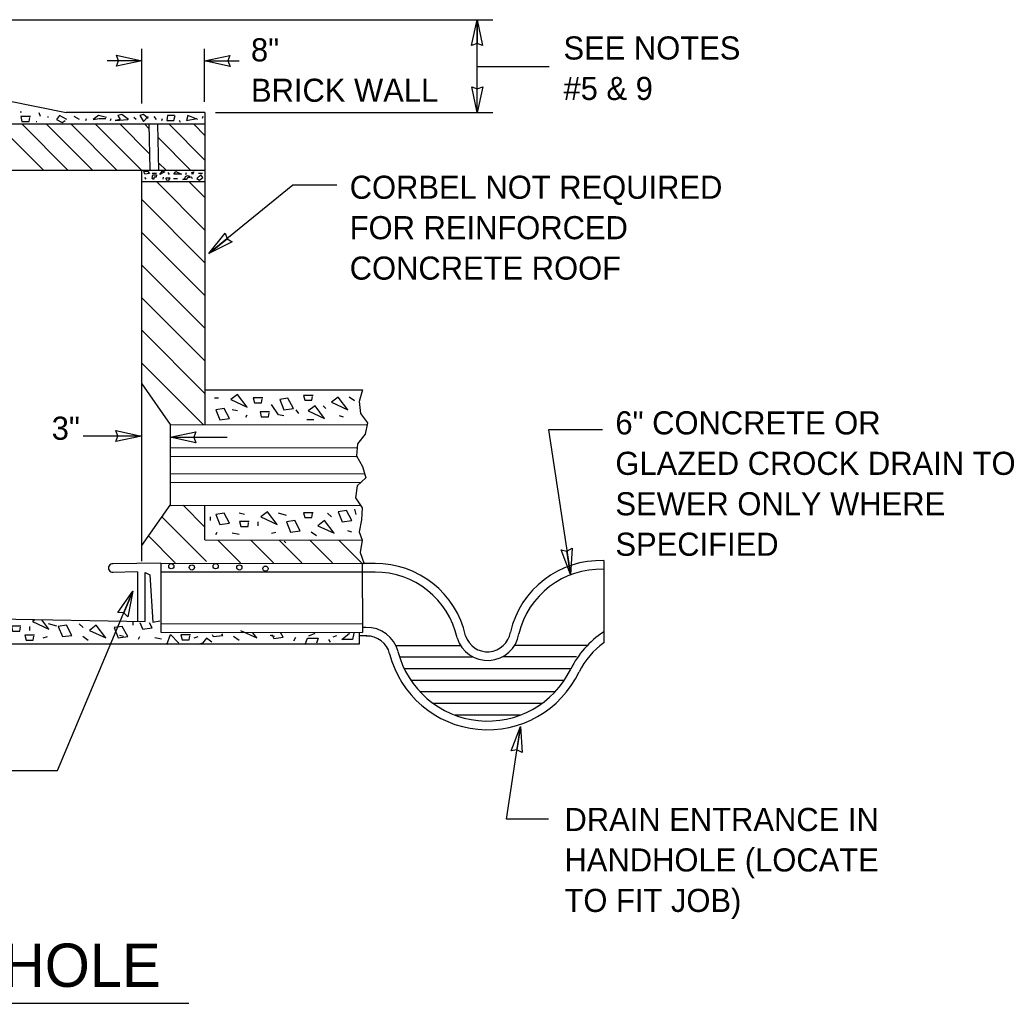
# Model space of a CAD drawing. Extents: x 19188 to 19495, y 20866 to 21061.
# Drawn here: x 19325.6 to 19361.63, y 20935.9 to 20971.54 of the extents above; entities that cross this region are included whole.
import ezdxf

# ---------------------------------------------------------------- set-up
doc = ezdxf.new("R2010")
doc.units = 0
doc.layers.add('G-ANNO-NOTE', color=7, linetype='Continuous')

msp = doc.modelspace()

# ---------------------------------------------------------------- linework, layer by layer
at = {"layer": 'G-ANNO-NOTE'}
for p, q in [((19324.256, 20971.541), (19342.735, 20971.541)), ((19342.169, 20968.19), (19342.169, 20971.544)), ((19342.169, 20971.544), (19342.169, 20970.691)), ((19330.022, 20968.516), (19330.022, 20970.493)), ((19332.286, 20968.578), (19332.286, 20970.493)), ((19330.022, 20970.061), (19328.758, 20970.061)), ((19330.022, 20970.061), (19329.17, 20970.061)), ((19332.286, 20970.061), (19333.55, 20970.061)), ((19332.286, 20970.061), (19333.139, 20970.061)), ((19342.169, 20969.859), (19344.787, 20969.859)), ((19342.169, 20968.19), (19342.169, 20969.043)), ((19325.184, 20968.609), (19327.279, 20968.19)), ((19332.306, 20968.19), (19327.279, 20968.19)), ((19332.306, 20968.19), (19332.306, 20956.881)), ((19332.685, 20968.19), (19342.735, 20968.19)), ((19306.277, 20967.771), (19332.306, 20967.771)), ((19327.341, 20966.096), (19325.665, 20967.771)), ((19326.554, 20967.771), (19328.23, 20966.096)), ((19327.443, 20967.771), (19329.114, 20966.1)), ((19330.007, 20966.096), (19328.34, 20967.762)), ((19329.22, 20967.771), (19330.288, 20966.703)), ((19330.109, 20967.771), (19330.271, 20967.608)), ((19330.316, 20966.119), (19330.283, 20967.766)), ((19330.63, 20966.096), (19330.597, 20967.764)), ((19332.306, 20966.462), (19330.997, 20967.771)), ((19332.306, 20967.351), (19331.886, 20967.771)), ((19326.452, 20966.096), (19325.264, 20967.284)), ((19331.784, 20966.096), (19330.617, 20967.262)), ((19330.895, 20966.096), (19330.625, 20966.366)), ((19306.277, 20966.096), (19332.306, 20966.096)), ((19330.002, 20966.096), (19330.002, 20951.919)), ((19330.085, 20966.044), (19330.228, 20966.058)), ((19330.128, 20965.948), (19330.085, 20966.044)), ((19330.295, 20965.975), (19330.128, 20965.948)), ((19330.228, 20966.058), (19330.295, 20965.975)), ((19330.388, 20965.797), (19330.413, 20965.921)), ((19330.438, 20965.756), (19330.388, 20965.797)), ((19330.396, 20965.986), (19330.544, 20965.986)), ((19330.413, 20965.921), (19330.547, 20965.921)), ((19330.463, 20965.838), (19330.438, 20965.756)), ((19330.539, 20965.838), (19330.463, 20965.838)), ((19330.547, 20965.921), (19330.539, 20965.838)), ((19330.673, 20965.934), (19330.749, 20966.058)), ((19330.849, 20966.03), (19330.673, 20965.934)), ((19330.749, 20966.058), (19330.849, 20966.03)), ((19331.05, 20965.811), (19330.883, 20965.811)), ((19330.883, 20965.811), (19330.9, 20965.742)), ((19331, 20965.729), (19331.05, 20965.811)), ((19331.167, 20965.794), (19331.315, 20965.794)), ((19331.176, 20965.948), (19331.244, 20966.044)), ((19331.453, 20965.948), (19331.176, 20965.948)), ((19331.244, 20966.044), (19331.453, 20965.948)), ((19331.504, 20965.756), (19331.588, 20965.811)), ((19331.588, 20965.811), (19331.596, 20965.866)), ((19331.596, 20965.866), (19331.671, 20965.907)), ((19331.688, 20965.825), (19331.621, 20965.756)), ((19331.671, 20965.907), (19331.747, 20965.88)), ((19331.764, 20965.825), (19331.688, 20965.825)), ((19331.747, 20965.88), (19331.764, 20965.825)), ((19331.831, 20966.016), (19331.898, 20966.03)), ((19331.856, 20965.934), (19331.831, 20966.016)), ((19331.898, 20966.03), (19331.856, 20965.934)), ((19332.15, 20965.921), (19332.016, 20965.797)), ((19332.016, 20965.797), (19332.108, 20965.729)), ((19332.074, 20965.986), (19332.222, 20965.986)), ((19332.108, 20965.729), (19332.234, 20965.825)), ((19332.234, 20965.825), (19332.15, 20965.921)), ((19332.306, 20965.677), (19330.002, 20965.677)), ((19332.306, 20963.922), (19330.559, 20965.669)), ((19330.9, 20965.742), (19331, 20965.729)), ((19331.579, 20965.756), (19331.504, 20965.756)), ((19331.621, 20965.756), (19331.579, 20965.756)), ((19332.306, 20965.107), (19331.735, 20965.678)), ((19335.486, 20965.557), (19332.445, 20963.07)), ((19337.08, 20965.557), (19335.486, 20965.557)), ((19332.306, 20962.737), (19330.004, 20965.039)), ((19332.306, 20961.552), (19330.006, 20963.852)), ((19332.445, 20963.07), (19333.105, 20963.61)), ((19332.306, 20960.367), (19330.008, 20962.665)), ((19332.306, 20959.182), (19330.01, 20961.478)), ((19332.306, 20957.997), (19330.012, 20960.291)), ((19332.237, 20956.881), (19330.014, 20959.104)), ((19330.016, 20958.349), (19331.043, 20956.881)), ((19332.306, 20958.136), (19338.018, 20958.127)), ((19333.49, 20957.961), (19333.244, 20957.778)), ((19333.835, 20957.504), (19333.49, 20957.961)), ((19337.135, 20957.87), (19336.889, 20957.686)), ((19337.48, 20957.412), (19337.135, 20957.87)), ((19337.726, 20957.732), (19337.529, 20957.87)), ((19332.801, 20957.824), (19332.653, 20957.824)), ((19333.244, 20957.778), (19333.835, 20957.504)), ((19334.968, 20957.229), (19334.722, 20957.595)), ((19335.313, 20957.824), (19335.017, 20957.778)), ((19335.017, 20957.778), (19335.165, 20957.412)), ((19335.51, 20957.458), (19335.313, 20957.824)), ((19336.298, 20957.55), (19336.052, 20957.366)), ((19336.643, 20957.092), (19336.298, 20957.55)), ((19336.692, 20957.458), (19336.593, 20957.55)), ((19336.889, 20957.686), (19337.48, 20957.412)), ((19332.998, 20957.458), (19332.702, 20957.412)), ((19332.702, 20957.412), (19332.85, 20957.047)), ((19333.195, 20957.092), (19332.998, 20957.458)), ((19333.49, 20957.366), (19333.293, 20957.412)), ((19333.786, 20957.138), (19333.835, 20957.229)), ((19335.165, 20957.184), (19334.968, 20957.229)), ((19335.165, 20957.412), (19335.51, 20957.458)), ((19335.707, 20957.275), (19335.608, 20957.412)), ((19336.052, 20957.366), (19336.643, 20957.092)), ((19337.332, 20957.138), (19337.185, 20957.184)), ((19331.052, 20956.881), (19331.021, 20956.912)), ((19331.043, 20956.881), (19338.167, 20956.869)), ((19331.049, 20956.881), (19331.049, 20953.949)), ((19332.85, 20957.047), (19333.195, 20957.092)), ((19336.249, 20957.047), (19336.002, 20957.047)), ((19330.002, 20956.456), (19327.89, 20956.456)), ((19330.002, 20956.456), (19329.149, 20956.456)), ((19331.049, 20956.415), (19333.105, 20956.415)), ((19331.049, 20956.415), (19331.902, 20956.415)), ((19346.712, 20956.684), (19344.756, 20956.684)), ((19344.756, 20956.684), (19345.553, 20951.441)), ((19331.041, 20956.043), (19337.796, 20956.032)), ((19331.064, 20955.729), (19337.795, 20955.718)), ((19331.064, 20955.101), (19338.078, 20955.089)), ((19331.064, 20954.787), (19337.946, 20954.775)), ((19331.038, 20953.949), (19330.006, 20952.484)), ((19331.038, 20953.949), (19337.944, 20953.937)), ((19332.306, 20953.153), (19331.51, 20953.949)), ((19332.306, 20952.69), (19332.306, 20953.949)), ((19332.998, 20953.663), (19332.702, 20953.618)), ((19332.702, 20953.618), (19332.85, 20953.252)), ((19333.195, 20953.298), (19332.998, 20953.663)), ((19333.737, 20953.618), (19333.54, 20953.663)), ((19334.574, 20953.709), (19334.328, 20953.527)), ((19334.918, 20953.252), (19334.574, 20953.709)), ((19335.263, 20953.572), (19334.968, 20953.663)), ((19336.741, 20953.663), (19336.889, 20953.527)), ((19337.43, 20953.755), (19337.135, 20953.709)), ((19337.135, 20953.709), (19337.283, 20953.343)), ((19337.627, 20953.389), (19337.43, 20953.755)), ((19337.726, 20953.801), (19337.776, 20953.618)), ((19332.361, 20951.913), (19330.748, 20953.526)), ((19332.506, 20953.389), (19332.506, 20953.527)), ((19332.85, 20953.252), (19333.195, 20953.298)), ((19334.229, 20953.206), (19334.229, 20953.343)), ((19334.328, 20953.527), (19334.918, 20953.252)), ((19335.559, 20953.389), (19335.263, 20953.343)), ((19335.263, 20953.343), (19335.411, 20952.978)), ((19335.756, 20953.024), (19335.559, 20953.389)), ((19336.642, 20953.389), (19336.396, 20953.206)), ((19336.396, 20953.206), (19336.988, 20952.932)), ((19336.988, 20952.932), (19336.642, 20953.389)), ((19337.283, 20953.343), (19337.627, 20953.389)), ((19331.224, 20951.865), (19330.255, 20952.834)), ((19332.702, 20952.886), (19332.751, 20952.978)), ((19333.54, 20952.886), (19333.293, 20952.932)), ((19334.722, 20952.932), (19334.869, 20952.978)), ((19335.411, 20952.978), (19335.756, 20953.024)), ((19336.347, 20952.841), (19336.15, 20952.978)), ((19337.627, 20952.978), (19337.48, 20953.024)), ((19332.306, 20952.69), (19338.009, 20952.68)), ((19333.596, 20951.863), (19332.776, 20952.683)), ((19334.787, 20951.857), (19333.978, 20952.666)), ((19335.813, 20951.857), (19335.004, 20952.666)), ((19335.239, 20952.591), (19335.179, 20952.65)), ((19336.922, 20951.857), (19336.113, 20952.666)), ((19337.976, 20951.857), (19337.167, 20952.666)), ((19345.553, 20951.441), (19345.425, 20952.284)), ((19330.706, 20951.854), (19328.971, 20951.83)), ((19330.706, 20951.854), (19330.701, 20949.341)), ((19330.706, 20951.854), (19338.007, 20951.842)), ((19338.007, 20951.842), (19338.017, 20949.329)), ((19338.479, 20951.838), (19338.027, 20951.834)), ((19346.759, 20951.939), (19346.759, 20948.962)), ((19329.859, 20951.528), (19328.954, 20951.515)), ((19329.859, 20951.528), (19329.859, 20949.746)), ((19330.133, 20949.734), (19330.142, 20951.514)), ((19330.142, 20951.514), (19330.308, 20951.423)), ((19330.308, 20951.423), (19330.419, 20949.711)), ((19330.705, 20951.54), (19338.007, 20951.528)), ((19338.479, 20951.524), (19337.994, 20951.525)), ((19326.959, 20944.333), (19329.693, 20950.836)), ((19329.693, 20950.836), (19329.362, 20950.05)), ((19306.277, 20950.176), (19330.133, 20949.734)), ((19326.141, 20949.797), (19326.053, 20949.732)), ((19326.053, 20949.732), (19326.644, 20949.458)), ((19326.644, 20949.458), (19326.394, 20949.79)), ((19326.932, 20949.561), (19326.636, 20949.653)), ((19327.285, 20949.595), (19326.989, 20949.549)), ((19327.481, 20949.229), (19327.285, 20949.595)), ((19327.743, 20949.653), (19327.891, 20949.516)), ((19328.368, 20949.595), (19328.122, 20949.412)), ((19328.713, 20949.138), (19328.368, 20949.595)), ((19329.698, 20949.595), (19329.698, 20949.732)), ((19329.948, 20949.693), (19330.038, 20949.469)), ((19330.387, 20949.504), (19330.292, 20949.68)), ((19330.419, 20949.711), (19330.669, 20949.756)), ((19330.702, 20949.655), (19338.004, 20949.643)), ((19325.954, 20949.412), (19325.954, 20949.549)), ((19326.989, 20949.549), (19327.137, 20949.184)), ((19327.137, 20949.184), (19327.481, 20949.229)), ((19328.122, 20949.412), (19328.713, 20949.138)), ((19329.308, 20949.558), (19329.013, 20949.513)), ((19329.013, 20949.513), (19329.161, 20949.147)), ((19329.353, 20949.184), (19329.205, 20949.23)), ((19329.505, 20949.193), (19329.308, 20949.558)), ((19330.043, 20949.458), (19330.387, 20949.504)), ((19330.701, 20949.341), (19338.017, 20949.329)), ((19330.918, 20948.899), (19331.057, 20949.26)), ((19331.057, 20949.26), (19331.362, 20948.944)), ((19332.57, 20949.266), (19332.604, 20949.184)), ((19332.604, 20949.184), (19332.948, 20949.229)), ((19332.948, 20949.229), (19332.916, 20949.29)), ((19333.589, 20949.412), (19334.18, 20949.138)), ((19334.18, 20949.138), (19334.042, 20949.321)), ((19334.82, 20949.184), (19334.672, 20949.23)), ((19334.734, 20949.266), (19334.796, 20949.116)), ((19335.14, 20949.161), (19335.048, 20949.333)), ((19336.076, 20949.215), (19336.298, 20949.305)), ((19337.075, 20949.215), (19336.936, 20949.17)), ((19337.269, 20949.079), (19337.546, 20949.305)), ((19337.705, 20949.315), (19337.657, 20949.079)), ((19337.906, 20948.92), (19337.906, 20949.329)), ((19338.174, 20949.208), (19337.912, 20949.208)), ((19338.14, 20949.514), (19338.024, 20949.514)), ((19303.344, 20948.92), (19337.906, 20948.92)), ((19326.447, 20949.138), (19326.595, 20949.184)), ((19328.073, 20949.046), (19327.876, 20949.184)), ((19329.161, 20949.147), (19329.505, 20949.193)), ((19329.895, 20949.092), (19329.944, 20949.184)), ((19330.732, 20949.092), (19330.486, 20949.138)), ((19331.914, 20949.138), (19332.062, 20949.184)), ((19332.222, 20948.944), (19332.056, 20948.899)), ((19332.36, 20949.124), (19332.222, 20948.944)), ((19332.554, 20948.989), (19332.36, 20949.124)), ((19333.54, 20949.046), (19333.343, 20949.184)), ((19334.796, 20949.116), (19335.14, 20949.161)), ((19335.521, 20949.034), (19335.605, 20949.17)), ((19335.938, 20948.899), (19336.021, 20949.124)), ((19336.021, 20949.124), (19336.409, 20949.124)), ((19336.409, 20949.124), (19336.354, 20948.944)), ((19336.853, 20948.989), (19336.797, 20949.079)), ((19337.657, 20949.079), (19337.269, 20949.079)), ((19339.225, 20948.868), (19341.556, 20948.868)), ((19346.149, 20948.868), (19343.553, 20948.868)), ((19339.392, 20948.449), (19342.005, 20948.449)), ((19345.766, 20948.449), (19343.086, 20948.449)), ((19339.525, 20948.03), (19345.55, 20948.03)), ((19339.758, 20947.611), (19345.333, 20947.611)), ((19340.107, 20947.192), (19344.984, 20947.192)), ((19340.574, 20946.773), (19344.501, 20946.773)), ((19341.372, 20946.354), (19343.719, 20946.354)), ((19343.235, 20942.568), (19343.743, 20945.929)), ((19343.743, 20945.929), (19343.615, 20945.086)), ((19321.853, 20944.333), (19326.959, 20944.333)), ((19344.756, 20942.568), (19343.235, 20942.568)), ((19298.859, 20935.899), (19331.72, 20935.899))]:
    msp.add_line(p, q, dxfattribs=at)
for points in [[(19342.169, 20970.691), (19341.965, 20970.616), (19342.169, 20971.544), (19342.364, 20970.618), (19342.169, 20970.691)], [(19329.169, 20970.061), (19329.095, 20970.264), (19330.022, 20970.061), (19329.097, 20969.866), (19329.169, 20970.061)], [(19333.139, 20970.061), (19333.213, 20969.857), (19332.286, 20970.061), (19333.212, 20970.255), (19333.139, 20970.061)], [(19342.169, 20969.043), (19342.373, 20969.118), (19342.169, 20968.19), (19341.974, 20969.116), (19342.169, 20969.043)], [(19325.607, 20968.214), (19325.65, 20968.214)], [(19325.976, 20968.038), (19325.628, 20968.038), (19325.672, 20967.861), (19325.932, 20967.861), (19325.954, 20968.003)], [(19326.344, 20968.038), (19326.301, 20968.179)], [(19326.626, 20968.003), (19326.626, 20968.038)], [(19327.299, 20967.932), (19327.039, 20968.073), (19326.93, 20967.932), (19327.125, 20967.826), (19327.234, 20967.897)], [(19327.754, 20967.932), (19327.559, 20968.038)], [(19327.993, 20967.897), (19328.015, 20967.968)], [(19328.731, 20968.003), (19328.448, 20968.073), (19328.253, 20967.932), (19328.47, 20967.968), (19328.709, 20967.968)], [(19328.882, 20967.897), (19328.904, 20967.968)], [(19329.533, 20967.932), (19329.294, 20968.108), (19329.143, 20968.073), (19329.23, 20967.932), (19329.056, 20967.897), (19329.512, 20967.932)], [(19329.815, 20967.932), (19329.729, 20968.003)], [(19330.249, 20967.968), (19330.076, 20968.108), (19329.946, 20968.073), (19330.076, 20967.861), (19330.249, 20968.038)], [(19330.553, 20967.932), (19330.466, 20968.038)], [(19330.748, 20967.897), (19330.77, 20967.968)], [(19331.204, 20968.073), (19330.943, 20968.073), (19330.922, 20967.897), (19331.182, 20967.897), (19331.225, 20968.073)], [(19332.05, 20967.932), (19331.681, 20968.073), (19331.638, 20967.897), (19332.007, 20967.968)], [(19332.223, 20968.038), (19332.201, 20967.968)], [(19326.193, 20967.861), (19326.214, 20967.861)], [(19331.421, 20967.826), (19331.377, 20967.897)], [(19330.17, 20965.764), (19330.126, 20965.834)], [(19330.785, 20965.775), (19330.806, 20965.845)], [(19331.017, 20965.942), (19330.974, 20966.013)], [(19331.615, 20965.939), (19331.638, 20966.01)], [(19331.857, 20965.777), (19331.813, 20965.848)], [(19333.105, 20963.61), (19333.292, 20963.5), (19332.445, 20963.07), (19333.038, 20963.806), (19333.105, 20963.61)], [(19336.225, 20957.929), (19335.878, 20957.929), (19335.922, 20957.753), (19336.182, 20957.753), (19336.204, 20957.894)], [(19338.018, 20958.127), (19337.899, 20957.704), (19337.944, 20957.269), (19338.196, 20956.93), (19338.107, 20956.519), (19337.839, 20956.18), (19337.795, 20955.745), (19338.018, 20955.358), (19338.137, 20954.946), (19337.825, 20954.656), (19337.766, 20954.221), (19338.003, 20953.858), (19337.974, 20953.423), (19337.899, 20952.988), (19338.009, 20952.68)], [(19334.403, 20957.838), (19334.055, 20957.838), (19334.099, 20957.662), (19334.36, 20957.662), (19334.381, 20957.803)], [(19334.649, 20957.335), (19334.302, 20957.335), (19334.345, 20957.159), (19334.606, 20957.159), (19334.627, 20957.3)], [(19329.149, 20956.456), (19329.074, 20956.66), (19330.002, 20956.456), (19329.076, 20956.262), (19329.149, 20956.456)], [(19331.903, 20956.415), (19331.977, 20956.21), (19331.049, 20956.415), (19331.975, 20956.609), (19331.903, 20956.415)], [(19336.225, 20953.678), (19335.878, 20953.678), (19335.922, 20953.501), (19336.182, 20953.501), (19336.204, 20953.643)], [(19333.91, 20953.358), (19333.563, 20953.358), (19333.606, 20953.182), (19333.867, 20953.182), (19333.888, 20953.323)], [(19338.009, 20952.68), (19337.934, 20952.235), (19338.073, 20951.829), (19338.007, 20951.842)], [(19345.425, 20952.285), (19345.615, 20952.389), (19345.553, 20951.441), (19345.221, 20952.327), (19345.425, 20952.285)], [(19329.362, 20950.049), (19329.145, 20950.06), (19329.693, 20950.836), (19329.514, 20949.907), (19329.362, 20950.049)], [(19325.636, 20949.563), (19325.288, 20949.563), (19325.332, 20949.387), (19325.592, 20949.387), (19325.614, 20949.528)], [(19326.123, 20949.234), (19325.775, 20949.234), (19325.819, 20949.058), (19326.08, 20949.058), (19326.101, 20949.199)], [(19331.782, 20949.248), (19331.435, 20949.248), (19331.478, 20949.071), (19331.738, 20949.071), (19331.759, 20949.212)], [(19343.615, 20945.086), (19343.402, 20945.042), (19343.743, 20945.929), (19343.797, 20944.985), (19343.615, 20945.086)]]:
    msp.add_lwpolyline(points, dxfattribs=at)
for centre in [(19331.085, 20951.739), (19331.833, 20951.694), (19332.693, 20951.739), (19333.553, 20951.694), (19334.496, 20951.649)]:
    msp.add_circle(centre, 0.0943, dxfattribs=at)
for centre, radius, start, end in [((19328.963, 20951.673), 0.157, 86.9969, 275.2119), ((19338.48, 20948.487), 3.351, 12.6062, 90.3359), ((19346.641, 20948.59), 3.351, 87.9811, 167.0084), ((19338.48, 20948.487), 3.037, 12.3658, 90.3719), ((19346.641, 20948.59), 3.037, 87.9808, 166.8227), ((19338.187, 20948.363), 1.152, 14.1283, 92.3449), ((19338.184, 20948.368), 0.838, 13.3365, 92.1982), ((19342.548, 20949.474), 1.152, 197.0101, 350.4094), ((19342.548, 20949.474), 0.838, 197.7909, 351.0123), ((19348.576, 20946.539), 3.351, 123.0622, 153.9668), ((19348.563, 20946.518), 3.037, 126.4226, 152.7455), ((19342.548, 20949.474), 3.666, 194.4193, 334.7191), ((19342.548, 20949.474), 3.351, 194.3466, 334.1083)]:
    msp.add_arc(centre, radius, start, end, dxfattribs=at)

# ---------------------------------------------------------------- texts
for s, height, p in [('8"', 0.8379, (19333.973, 20970.04)), ('SEE NOTES', 0.8379, (19345.3, 20970.106)), ('BRICK WALL', 0.8379, (19333.973, 20968.574)), ('#5 & 9', 0.8379, (19345.3, 20968.64)), ('CORBEL NOT REQUIRED', 0.83785, (19337.551, 20965.058)), ('FOR REINFORCED', 0.83785, (19337.551, 20963.592)), ('CONCRETE ROOF', 0.83785, (19337.551, 20962.126)), ('3"', 0.8379, (19326.751, 20956.322)), ('6" CONCRETE OR ', 0.83785, (19347.182, 20956.516)), ('GLAZED CROCK DRAIN TO ', 0.83785, (19347.182, 20955.049)), ('SEWER ONLY WHERE ', 0.83785, (19347.182, 20953.583)), ('SPECIFIED', 0.8379, (19347.182, 20952.116)), ('DRAIN ENTRANCE IN', 0.83785, (19345.336, 20942.137)), ('HANDHOLE (LOCATE', 0.83785, (19345.336, 20940.671)), ('TO FIT JOB)', 0.83785, (19345.336, 20939.204)), ('SECTION TYPE "D" HANDHOLE', 1.57098, (19299.445, 20936.487))]:
    msp.add_text(s, height=height, dxfattribs=at).set_placement(p)

doc.saveas('drawing.dxf')
